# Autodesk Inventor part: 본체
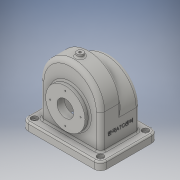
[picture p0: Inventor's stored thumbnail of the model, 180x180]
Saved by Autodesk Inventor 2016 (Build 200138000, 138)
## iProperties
Created: 2017-11
Part Number: 본체
Material: 일반
Document SubType Name: Modeling
Designer: 605-06
Density: 1 g/cm^3
Appearance: 기본값
Author: 605-06
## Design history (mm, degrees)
sketch "스케치1"
  geometry: L1 (-75, 55)-(75, 55); L2 (75, 55)-(75, -55); L3 (75, -55)-(-75, -55); L4 (-75, -55)-(-75, 55); L5 (-75, 55)-(75, -55); L6 (75, 55)-(-75, -55); 1 further point
  constraints: 12 end point, 2 midpoint, 2 parallel, 1 horizontal, 1 perpendicular
  dimensions: "d0" = 150 distance of L2.end L3.end; "d1" = 110 distance of L1.end L2.end
extrude "돌출1" new body sketch "스케치1" distance "d2" = 15; taper "d3" = 0 deg
node "작업 평면1"
sketch "스케치2"
  geometry: L1 (17, 80)-(17, 0); L2 (17, 0)-(133, 0); L3 (133, 0)-(133, 80); L4 (0, 0)-(150, 0) reference; L5 (17, 57)-(17, 0); L6 (17, 0)-(133, 0); L7 (133, 0)-(133, 57); L8 (22, 80)-(22, 5); L9 (22, 5)-(128, 5); L10 (128, 5)-(128, 80); L11 (22, 57)-(22, 5); L12 (22, 5)-(128, 5); L13 (128, 5)-(128, 57); L14 (0.997, 14.58)-(140.524, 14.58); L15 (133, 80)-(133, 0); L16 (133, 0)-(17, 0); L17 (17, 0)-(17, 80); L18 (150, 0)-(0, 0); L19 (22, 80)-(22, 5); L20 (22, 5)-(128, 5); L21 (128, 5)-(128, 80); L22 (133, 57)-(133, 0); L23 (133, 0)-(17, 0); L24 (17, 0)-(17, 57); L25 (22, 57)-(22, 5); L26 (22, 5)-(128, 5); L27 (128, 5)-(128, 57); A1 r 58 centre (75, 80) between (133, 80) and (17, 80); A2 r 58 centre (75, 57) between (133, 57) and (17, 57); A3 r 53 centre (75, 80) between (128, 80) and (22, 80); A4 r 53 centre (75, 57) between (128, 57) and (22, 57); A5 r 58 centre (75, 80) between (133, 80) and (17, 80); A6 r 53 centre (75, 80) between (128, 80) and (22, 80); A7 r 58 centre (75, 57) between (133, 57) and (17, 57); A8 r 53 centre (75, 57) between (128, 57) and (22, 57); 4 further points
  constraints: 52 end point, 16 perpendicular, 16 point on circle, 8 centre point, 6 midpoint, 4 vertical, 1 coincident, 1 vertical alignment, 12 other
  dimensions: "d5" = 116 distance of L2.end L1.end; "d6" = 80 vertical distance of L2.end A1.centre; "d7" = 58 radius of A1; "d8" = 80 distance of L1.end L1.start; "d9" = 58 radius of A2; "d10" = 116 distance of L5.end L6.end; "d11" = 57 vertical distance of L6.end A2.centre; "d12" = 57 distance of L5.end L5.start; "d17" = 5 radial gap between concentric circles of A1 A3; "d18" = 5 radial gap between concentric circles of A2 A4; "d50" = 116 distance of L16.end L15.end; "d51" = 80 vertical distance of L16.end A5.centre; "d52" = 5 radial gap between concentric circles of A5 A6; "d53" = 75 distance of L20.end L21.end; "d54" = 53 radius of A6; "d55" = 57 vertical distance of A7.centre L23.end; "d56" = 57 distance of L22.end L22.start; "d57" = 58 radius of A7; "d58" = 116 distance of L22.end L23.end; "d59" = 5 radial gap between concentric circles of A7 A8
extrude "돌출2" join sketch "스케치2" distance "d13" = 38; taper "d14" = 0 deg
extrude "돌출3" join sketch "스케치2" distance "d15" = 38; taper "d16" = 0 deg
node "작업 평면2"
sketch "스케치3"
  geometry: L1 (0.997, 14.58)-(140.524, 14.58); L2 (133, 80)-(133, 0); L3 (133, 0)-(17, 0); L4 (17, 0)-(17, 80); L5 (150, 0)-(0, 0) reference; L6 (22, 80)-(22, 5); L7 (22, 5)-(128, 5); L8 (128, 5)-(128, 80); L9 (133, 57)-(133, 0); L10 (133, 0)-(17, 0); L11 (17, 0)-(17, 57); L12 (22, 57)-(22, 5); L13 (22, 5)-(128, 5); L14 (128, 5)-(128, 57); A1 r 58 centre (75, 80) between (133, 80) and (17, 80); A2 r 53 centre (75, 80) between (128, 80) and (22, 80); A3 r 58 centre (75, 57) between (133, 57) and (17, 57); A4 r 53 centre (75, 57) between (128, 57) and (22, 57); 1 further point
  constraints: 26 end point, 8 perpendicular, 8 point on circle, 4 centre point, 3 midpoint, 2 vertical, 6 other
  dimensions: "d30" = 116 distance of L3.end L2.end; "d34" = 80 vertical distance of L3.end A1.centre; "d35" = 5 radial gap between concentric circles of A1 A2; "d36" = 75 distance of L7.end L8.end; "d37" = 53 radius of A2; "d38" = 57 vertical distance of A3.centre L10.end; "d39" = 57 distance of L9.end L9.start; "d40" = 58 radius of A3; "d41" = 116 distance of L9.end L10.end; "d42" = 5 radial gap between concentric circles of A3 A4
extrude "돌출5" cut sketch "스케치2" distance "d45" = 33; taper "d46" = 0 deg
node "작업 평면3"
sketch "스케치5"
  geometry: L1 (-133, 80)-(-133, 0); L2 (-133, 0)-(-17, 0); L3 (-17, 0)-(-17, 80); L4 (-128, 80)-(-128, 5); L5 (-128, 5)-(-22, 5); L6 (-22, 5)-(-22, 80); A1 r 58 centre (-75, 80) between (-17, 80) and (-133, 80); A2 r 53 centre (-75, 80) between (-22, 80) and (-128, 80); 2 further points
  constraints: 12 end point, 4 perpendicular, 4 point on circle, 2 centre point, 1 coincident, 1 midpoint, 1 vertical, 3 other
  dimensions: "d60" = 80 vertical distance of L2.end A1.centre; "d61" = 116 distance of L2.end L1.end; "d62" = 58 radius of A1; "d63" = 80 distance of L1.end L1.start; "d64" = 5 radial gap between concentric circles of A1 A2
extrude "돌출7" cut sketch "스케치5" distance "d65" = 28; taper "d66" = 0 deg
sketch "스케치6"
  geometry: L1 (-133, 0)-(-17, 0); L2 (-17, 0)-(-17, 57); L3 (-133, 57)-(-133, 0); L4 (-128, 57)-(-128, 5); L5 (-128, 5)-(-22, 5); L6 (-22, 5)-(-22, 57); L7 (-22, 0)-(-128, 0) reference; A1 r 58 centre (-75, 57) between (-17, 57) and (-133, 57); A2 r 53 centre (-75, 57) between (-22, 57) and (-128, 57); 1 further point
  constraints: 12 end point, 4 point on circle, 2 centre point, 2 perpendicular, 1 horizontal, 1 horizontal alignment, 1 midpoint, 3 other
  dimensions: "d67" = 57 vertical distance of A1.centre L1.end; "d68" = 116 distance of L1.end L1.start; "d69" = 57 distance of L1.start L3.start; "d70" = 58 radius of A1; "d71" = 5 radial gap between concentric circles of A1 A2
extrude "돌출8" cut sketch "스케치6" distance "d72" = 10; taper "d73" = 0 deg
sketch "스케치7"
  geometry: L1 (-53, -33)-(53, -33) reference; L2 (-53, -33)-(53, -33); L3 (53, -33)-(53, 33) reference; L4 (53, -33)-(53, 33); L5 (53, 33)-(-53, 33) reference; L6 (53, 33)-(-53, 33); L7 (-53, -33)-(-53, 33) reference; L8 (-53, 33)-(-53, -33); 1 further point
  constraints: 8 end point, 4 collinear
extrude "돌출9" cut sketch "스케치7" distance "d74" = 20; taper "d75" = 0 deg
sketch "스케치8"
  geometry: L1 (0, 0)-(-150, 0) reference; C1 r 31 at (-75, 65); C2 r 16 at (-75, 65); 2 further points
  constraints: 2 centre point, 1 coincident, 1 midpoint, 1 vertical alignment
  dimensions: "d76" = 62 diameter of C1; "d77" = 32 diameter of C2; "d78" = 65 distance from line of L1 C1.centre
extrude "돌출10" join sketch "스케치8" distance "d79" = 10; taper "d80" = 0 deg
extrude "돌출11" cut sketch "스케치8" stored distance "d81" = 30; taper "d82" = 0 deg
sketch "스케치9"
  geometry: L1 (150, 0)-(0, 0) reference; C1 r 37.5 at (75, 65); C2 r 16 at (75, 65); 2 further points
  constraints: 2 centre point, 1 coincident, 1 midpoint, 1 vertical alignment
  dimensions: "d83" = 75 diameter of C1; "d84" = 32 diameter of C2; "d85" = 65 distance from line of L1 C1.centre
extrude "돌출12" join sketch "스케치9" distance "d86" = 9; taper "d87" = 0 deg
extrude "돌출13" cut sketch "스케치9" stored distance "d88" = 30; taper "d89" = 0 deg
node "작업 평면4"
sketch "스케치10"
  geometry: L1 (-37.5, 33)-(37.5, 33) reference; L2 (58, -5)-(-58, -5) reference; L3 (0, 33)-(0, -5); C1 r 6 at (0, 14); 1 further point
  constraints: 2 end point, 2 midpoint, 1 centre point, 1 coincident, 1 perpendicular
  dimensions: "d90" = 12 diameter of C1
extrude "돌출14" join sketch "스케치10" distance "d91" = 11; taper "d92" = 0 deg
sketch "스케치11"
  geometry: L1 (-58, -19)-(58, -19) reference; 3 further points
  constraints: 1 midpoint, 1 vertical alignment
  dimensions: "d93" = 19 distance from line of L1 point (0, 0)
hole "구멍1" sketch "스케치11" at (0, 0) diameter "d94" = 4.459; stored, may be unused: countersink angle "d98" = 90 deg, drill point angle "d100" = 118 deg; dims "d95" = 10, "d96" = 4, "d97" = 2, "d99" = 12.8
sketch "스케치12" dims "d101" = 58
  geometry: C1 r 37.5 at (0, 0) reference; 3 further points
  constraints: 2 vertical alignment, 1 coincident, 2 other
hole "구멍2" sketch "스케치12" at (0, 29) diameter "d102" = 2.459; stored, may be unused: countersink angle "d106" = 90 deg, drill point angle "d108" = 118 deg; dims "d103" = 6, "d104" = 4, "d105" = 2, "d107" = 8
sketch "스케치13" dims "d112" = 52
  geometry: C1 r 31 at (0, 0) reference; 3 further points
  constraints: 2 vertical alignment, 1 coincident, 2 other
hole "구멍3" sketch "스케치13" at (0, 26) diameter "d113" = 2.459; stored, may be unused: countersink angle "d117" = 90 deg, drill point angle "d119" = 118 deg; dims "d114" = 6, "d115" = 4, "d116" = 2, "d118" = 8
fillet "모깎기1" dims "d123" = 12
sketch "스케치14"
  geometry: A1 r 12 centre (-63, -43) between (-75, -43) and (-63, -55) reference; 2 further points
  constraints: 1 coincident
hole "구멍4" sketch "스케치14" at (-63, -43) diameter "d124" = 5; stored, may be unused: countersink angle "d128" = 90 deg, drill point angle "d130" = 118 deg; dims "d125" = 6, "d126" = 12, "d127" = 5, "d129" = 15
node "작업 평면5"
sketch "스케치15"
  geometry: L1 (0, 0)-(0, 65) reference; 2 further points
  constraints: 1 other
  dimensions: "d138" = 40 distance of point (38, -15) point (38, 25); "d139" = 38 distance from line of L1 point (38, 25)
feature "엠보싱1" sketch "스케치15" dims "d9" = 58, "d10" = 116, "d11" = 57, "d12" = 57, "d18" = 5, "d140" = 0.5, "d141" = 0
fillet "모깎기2" dims "d142" = 3
fillet "모깎기3" dims "d143" = 8
fillet "모깎기4" dims "d144" = 3
fillet "모깎기5" dims "d145" = 3
fillet "모깎기6" dims "d146" = 3
fillet "모깎기7" dims "d147" = 3
node "솔리드1"
pattern_circular "원형 패턴1" dims angle "d110" = 360 deg
pattern_circular "원형 패턴2" dims angle "d121" = 360 deg
pattern_linear "직사각형 패턴1" dims "d133" = 86, "d136" = 126
other parameters: "d4" = -55, "d19" = 5, "d49" = -5
